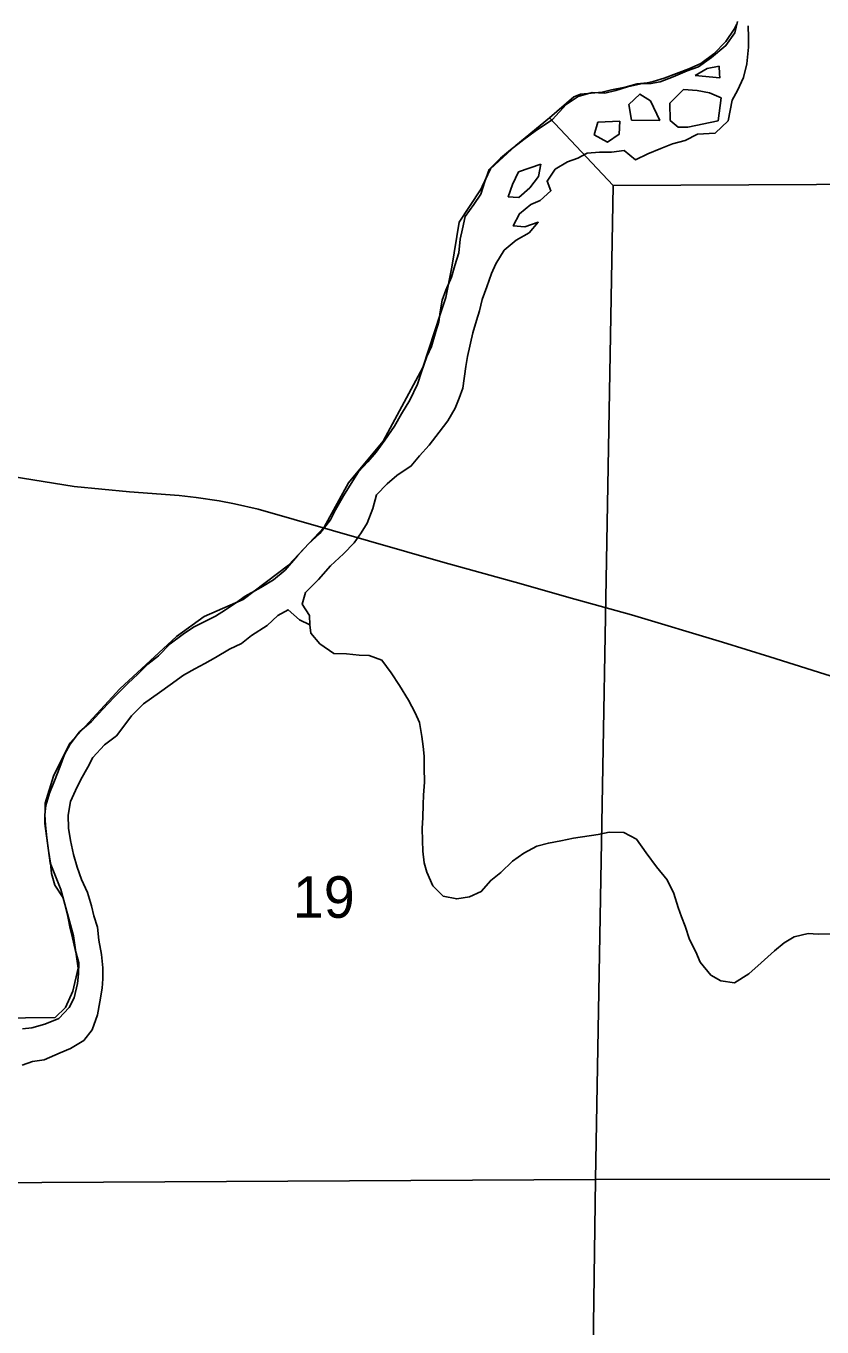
# Model space of a CAD drawing. Extents: x 1772825 to 1773716, y 1138558 to 1139032.
# Drawn here: x 1772828.223 to 1772828.624, y 1138562.068 to 1138562.723 of the extents above; entities that cross this region are included whole.
import ezdxf

# ---------------------------------------------------------------- set-up
doc = ezdxf.new("R2010")
doc.units = 0
for name, color, linetype in [('GM_X_Major_River', 7, 'Continuous'), ('GM_X_Minor_River', 7, 'Continuous'), ('GM_X_Rail_Line', 7, 'Continuous'), ('GM_X_Section', 7, 'Continuous'), ('GM_X_Section_Text', 7, 'Continuous')]:
    doc.layers.add(name, color=color, linetype=linetype)

msp = doc.modelspace()

# ---------------------------------------------------------------- linework, layer by layer
at = {"layer": 'GM_X_Major_River'}
msp.add_line((1772828.52194, 1138562.67523), (1772828.51074, 1138562.67475), dxfattribs=at)
for points in [[(1772828.58108, 1138562.72538), (1772828.57972, 1138562.7197), (1772828.57532, 1138562.71327), (1772828.56809, 1138562.70724), (1772828.56143, 1138562.70253), (1772828.55573, 1138562.70048), (1772828.54871, 1138562.69748), (1772828.54225, 1138562.69505), (1772828.53751, 1138562.69413), (1772828.5324, 1138562.69397), (1772828.52576, 1138562.69249), (1772828.51988, 1138562.69063), (1772828.51438, 1138562.68933), (1772828.50794, 1138562.68956), (1772828.50092, 1138562.6877), (1772828.49483, 1138562.68356), (1772828.48804, 1138562.67598)], [(1772828.57636, 1138562.6753), (1772828.57837, 1138562.68572), (1772828.58105, 1138562.69065), (1772828.58413, 1138562.69727), (1772828.58587, 1138562.7041), (1772828.58668, 1138562.71244), (1772828.58671, 1138562.71738), (1772828.58656, 1138562.72327)], [(1772828.57207, 1138562.69904), (1772828.57185, 1138562.70285), (1772828.56578, 1138562.70175), (1772828.55989, 1138562.69817)], [(1772828.55989, 1138562.69817), (1772828.57219, 1138562.69696), (1772828.57207, 1138562.69904)], [(1772828.542, 1138562.67556), (1772828.53727, 1138562.6854), (1772828.53199, 1138562.68885), (1772828.52646, 1138562.68356), (1772828.5278, 1138562.67567)], [(1772828.57132, 1138562.67534), (1772828.57289, 1138562.6869), (1772828.56703, 1138562.6894), (1772828.56079, 1138562.69058), (1772828.55397, 1138562.69119), (1772828.54714, 1138562.68424), (1772828.54722, 1138562.67553)], [(1772828.48804, 1138562.67598), (1772828.47922, 1138562.67024), (1772828.47349, 1138562.66592), (1772828.46682, 1138562.66085), (1772828.46185, 1138562.65652), (1772828.45612, 1138562.65087), (1772828.45399, 1138562.64482), (1772828.45185, 1138562.63838), (1772828.4484, 1138562.63329), (1772828.44399, 1138562.62725), (1772828.44262, 1138562.621), (1772828.44144, 1138562.61588), (1772828.44082, 1138562.60887), (1772828.43888, 1138562.60262), (1772828.43713, 1138562.59675), (1772828.43424, 1138562.59013), (1772828.43249, 1138562.58502), (1772828.4315, 1138562.57915), (1772828.43071, 1138562.57422), (1772828.42934, 1138562.5693), (1772828.42701, 1138562.56172), (1772828.4247, 1138562.55681), (1772828.42199, 1138562.54905), (1772828.42004, 1138562.5428), (1772828.41619, 1138562.53467), (1772828.41197, 1138562.52787), (1772828.40851, 1138562.52164), (1772828.40352, 1138562.51465), (1772828.3993, 1138562.50862), (1772828.39509, 1138562.50371), (1772828.39031, 1138562.49863), (1772828.38571, 1138562.49145), (1772828.38283, 1138562.48654), (1772828.37879, 1138562.47955), (1772828.37629, 1138562.47445), (1772828.37093, 1138562.46766), (1772828.365, 1138562.4622), (1772828.35965, 1138562.45636), (1772828.35334, 1138562.44919), (1772828.34761, 1138562.4443), (1772828.34113, 1138562.44037), (1772828.33332, 1138562.43606), (1772828.32836, 1138562.4325), (1772828.3234, 1138562.42912), (1772828.31826, 1138562.42593), (1772828.31235, 1138562.42294), (1772828.30721, 1138562.42051), (1772828.30206, 1138562.41695), (1772828.29558, 1138562.41206), (1772828.28965, 1138562.40604), (1772828.28431, 1138562.4019), (1772828.27934, 1138562.39701), (1772828.27418, 1138562.39211), (1772828.2673, 1138562.38515), (1772828.26157, 1138562.37912), (1772828.25583, 1138562.3729), (1772828.24991, 1138562.36782), (1772828.24512, 1138562.3616), (1772828.24224, 1138562.35631), (1772828.23991, 1138562.35006), (1772828.23721, 1138562.34306), (1772828.2347, 1138562.33682), (1772828.23295, 1138562.33076), (1772828.23234, 1138562.32602), (1772828.23268, 1138562.32071), (1772828.23339, 1138562.31444), (1772828.2343, 1138562.30798), (1772828.2352, 1138562.30171), (1772828.23573, 1138562.2964), (1772828.2374, 1138562.2905), (1772828.24171, 1138562.28421), (1772828.24392, 1138562.27489), (1772828.24521, 1138562.26881), (1772828.24631, 1138562.26406), (1772828.2476, 1138562.25817), (1772828.24945, 1138562.25151), (1772828.24941, 1138562.24601), (1772828.2488, 1138562.24108), (1772828.24723, 1138562.23388), (1772828.24473, 1138562.22897), (1772828.23938, 1138562.22351), (1772828.23234, 1138562.22053), (1772828.22587, 1138562.21868), (1772828.22112, 1138562.21833)], [(1772828.2402, 1138562.20624), (1772828.24534, 1138562.20828), (1772828.25201, 1138562.21241), (1772828.25622, 1138562.21769), (1772828.25893, 1138562.22526), (1772828.26012, 1138562.23189), (1772828.26131, 1138562.23871), (1772828.26153, 1138562.24345), (1772828.26157, 1138562.24895), (1772828.26086, 1138562.2556), (1772828.25958, 1138562.26282), (1772828.25887, 1138562.26947), (1772828.25702, 1138562.27517), (1772828.25591, 1138562.28012), (1772828.25388, 1138562.28696), (1772828.25089, 1138562.29344), (1772828.24866, 1138562.29971), (1772828.24681, 1138562.30599), (1772828.24534, 1138562.31302), (1772828.24425, 1138562.31929), (1772828.2441, 1138562.32574), (1772828.24529, 1138562.33276), (1772828.2478, 1138562.33824), (1772828.25049, 1138562.34372), (1772828.25414, 1138562.34995), (1772828.25665, 1138562.35487), (1772828.26239, 1138562.36128), (1772828.26849, 1138562.36578), (1772828.27213, 1138562.37069), (1772828.27596, 1138562.37578), (1772828.28208, 1138562.38181), (1772828.29009, 1138562.38763), (1772828.29543, 1138562.39138), (1772828.30229, 1138562.39626), (1772828.30801, 1138562.39945), (1772828.31296, 1138562.40226), (1772828.3183, 1138562.40525), (1772828.32535, 1138562.40937), (1772828.33144, 1138562.41217), (1772828.3364, 1138562.41631), (1772828.34441, 1138562.42137), (1772828.34975, 1138562.42626), (1772828.3549, 1138562.42926), (1772828.36055, 1138562.42409), (1772828.36585, 1138562.42159), (1772828.36569, 1138562.42633), (1772828.36194, 1138562.43205), (1772828.36369, 1138562.43792), (1772828.37019, 1138562.44451), (1772828.37631, 1138562.4513), (1772828.3828, 1138562.45732), (1772828.38816, 1138562.46297), (1772828.39161, 1138562.46788), (1772828.39468, 1138562.47279), (1772828.39758, 1138562.48017), (1772828.39934, 1138562.48717), (1772828.40469, 1138562.49264), (1772828.40965, 1138562.49677), (1772828.4169, 1138562.50165), (1772828.42111, 1138562.50674), (1772828.42589, 1138562.51202), (1772828.43087, 1138562.51862), (1772828.43528, 1138562.52428), (1772828.43893, 1138562.53071), (1772828.44105, 1138562.53581), (1772828.4428, 1138562.54073), (1772828.44439, 1138562.55173), (1772828.44519, 1138562.55665), (1772828.44793, 1138562.56859), (1772828.44968, 1138562.57483), (1772828.45124, 1138562.57976), (1772828.45261, 1138562.58544), (1772828.45493, 1138562.59187), (1772828.45726, 1138562.5985), (1772828.45938, 1138562.60341), (1772828.4636, 1138562.61021), (1772828.46971, 1138562.61529), (1772828.47619, 1138562.61904), (1772828.48078, 1138562.62431), (1772828.47412, 1138562.62209), (1772828.46824, 1138562.62251), (1772828.47132, 1138562.62856), (1772828.47705, 1138562.63326), (1772828.48181, 1138562.63531), (1772828.48716, 1138562.6402), (1772828.48529, 1138562.64496), (1772828.48932, 1138562.651), (1772828.49561, 1138562.65475), (1772828.50075, 1138562.65661), (1772828.50551, 1138562.65904), (1772828.51158, 1138562.65956), (1772828.51765, 1138562.65952), (1772828.52411, 1138562.66042), (1772828.52977, 1138562.65582), (1772828.53605, 1138562.65881), (1772828.54252, 1138562.66142), (1772828.54842, 1138562.66384), (1772828.5547, 1138562.6655), (1772828.56098, 1138562.66868), (1772828.56984, 1138562.66918), (1772828.57636, 1138562.6753)], [(1772828.51074, 1138562.67475), (1772828.50899, 1138562.66831), (1772828.51561, 1138562.66466), (1772828.52152, 1138562.6686), (1772828.52194, 1138562.67523)], [(1772828.5278, 1138562.67567), (1772828.542, 1138562.67556)], [(1772828.54722, 1138562.67553), (1772828.55133, 1138562.67217), (1772828.55607, 1138562.67213), (1772828.57132, 1138562.67534)], [(1772828.48213, 1138562.65352), (1772828.47091, 1138562.64962), (1772828.46783, 1138562.64339), (1772828.46569, 1138562.63714), (1772828.46827, 1138562.63694)], [(1772828.46827, 1138562.63694), (1772828.471, 1138562.63672), (1772828.47654, 1138562.64161), (1772828.48095, 1138562.64727), (1772828.48213, 1138562.65352)], [(1772828.22099, 1138562.19993), (1772828.22613, 1138562.20179), (1772828.23202, 1138562.20269), (1772828.2402, 1138562.20624)]]:
    msp.add_lwpolyline(points, dxfattribs=at)
at = {"layer": 'GM_X_Minor_River'}
msp.add_lwpolyline([(1772828.36585, 1138562.42159), (1772828.36639, 1138562.41741), (1772828.3709, 1138562.41206), (1772828.37789, 1138562.40726), (1772828.38434, 1138562.40703), (1772828.39059, 1138562.40641), (1772828.39572, 1138562.40618), (1772828.40215, 1138562.40385), (1772828.40685, 1138562.39756), (1772828.41097, 1138562.39108), (1772828.41547, 1138562.38364), (1772828.41884, 1138562.37735), (1772828.42108, 1138562.3724), (1772828.42217, 1138562.36537), (1772828.42289, 1138562.36044), (1772828.42343, 1138562.3555), (1772828.42338, 1138562.34962), (1772828.42352, 1138562.3424), (1772828.4231, 1138562.33596), (1772828.42287, 1138562.33122), (1772828.42263, 1138562.32458), (1772828.4224, 1138562.31907), (1772828.42255, 1138562.313), (1772828.4227, 1138562.30769), (1772828.42342, 1138562.3018), (1772828.42471, 1138562.29705), (1772828.4277, 1138562.29019), (1772828.43297, 1138562.28503), (1772828.43979, 1138562.28365), (1772828.44625, 1138562.28474), (1772828.45215, 1138562.28735), (1772828.45694, 1138562.29301), (1772828.4619, 1138562.29695), (1772828.46782, 1138562.3026), (1772828.47354, 1138562.30673), (1772828.48002, 1138562.31029), (1772828.48591, 1138562.31176), (1772828.49218, 1138562.31285), (1772828.49864, 1138562.31432), (1772828.51099, 1138562.31613), (1772828.5165, 1138562.31722), (1772828.5239, 1138562.31717), (1772828.53032, 1138562.3137), (1772828.53521, 1138562.30684), (1772828.54028, 1138562.29978), (1772828.54573, 1138562.29329), (1772828.5491, 1138562.28643), (1772828.55133, 1138562.27939), (1772828.553, 1138562.27464), (1772828.55486, 1138562.26988), (1772828.5569, 1138562.26322), (1772828.56008, 1138562.25694), (1772828.56232, 1138562.2518), (1772828.56777, 1138562.2453), (1772828.57269, 1138562.24242), (1772828.5797, 1138562.24142), (1772828.58675, 1138562.24592), (1772828.59306, 1138562.25156), (1772828.59974, 1138562.25759), (1772828.6047, 1138562.26153), (1772828.60966, 1138562.26453), (1772828.61669, 1138562.26619), (1772828.62181, 1138562.26596), (1772828.62788, 1138562.2661)], dxfattribs=at)
at = {"layer": 'GM_X_Rail_Line'}
for points in [[(1772828.16182, 1138562.50319), (1772828.21603, 1138562.49624), (1772828.24712, 1138562.49124), (1772828.27498, 1138562.48855), (1772828.30004, 1138562.48673), (1772828.30855, 1138562.48569), (1772828.3202, 1138562.48404), (1772828.32789, 1138562.48261), (1772828.33976, 1138562.47987), (1772828.43277, 1138562.45322)], [(1772828.43277, 1138562.45322), (1772828.47216, 1138562.4423), (1772828.4962, 1138562.43544), (1772828.52782, 1138562.42662), (1772828.57356, 1138562.41289), (1772828.59734, 1138562.4055), (1772828.63738, 1138562.393)]]:
    msp.add_lwpolyline(points, dxfattribs=at)
at = {"layer": 'GM_X_Section'}
for points in [[(1772829.04388, 1138563.14186), (1772829.03068, 1138562.64534), (1772828.51851, 1138562.64277), (1772828.4865, 1138562.67693), (1772828.49871, 1138562.68748), (1772828.50213, 1138562.68878), (1772828.51294, 1138562.68983), (1772828.51768, 1138562.69093), (1772828.52452, 1138562.6924), (1772828.53059, 1138562.69406), (1772828.53571, 1138562.69458), (1772828.53875, 1138562.69513), (1772828.54426, 1138562.69679), (1772828.55661, 1138562.70162), (1772828.56269, 1138562.70423), (1772828.56917, 1138562.70911), (1772828.57528, 1138562.71531), (1772828.5795, 1138562.72153), (1772828.58084, 1138562.72399)], [(1772827.98424, 1138562.22106), (1772828.23758, 1138562.22388), (1772828.24274, 1138562.22896), (1772828.24659, 1138562.23727), (1772828.24914, 1138562.2488), (1772828.2468, 1138562.26512), (1772828.24053, 1138562.28847), (1772828.23514, 1138562.30177), (1772828.23245, 1138562.32169), (1772828.23252, 1138562.33192), (1772828.23679, 1138562.34553), (1772828.24507, 1138562.36214), (1772828.2701, 1138562.38942), (1772828.29872, 1138562.41573), (1772828.31262, 1138562.42586), (1772828.3322, 1138562.43443), (1772828.35507, 1138562.45169), (1772828.37303, 1138562.47088), (1772828.38532, 1138562.49314), (1772828.40272, 1138562.51404), (1772828.42271, 1138562.55122), (1772828.43163, 1138562.57843), (1772828.43434, 1138562.58637), (1772828.4373, 1138562.6017), (1772828.44107, 1138562.62441), (1772828.4518, 1138562.64062), (1772828.45257, 1138562.64232), (1772828.45681, 1138562.65119), (1772828.46959, 1138562.66303), (1772828.4865, 1138562.67693), (1772828.51851, 1138562.64277), (1772828.50962, 1138562.14244), (1772827.98305, 1138562.13959)]]:
    msp.add_lwpolyline(points, dxfattribs=at)
for points in [[(1772829.03068, 1138562.64534), (1772829.02215, 1138562.14292), (1772828.50962, 1138562.14244), (1772828.51851, 1138562.64277)], [(1772828.50962, 1138562.14244), (1772828.50281, 1138561.64361), (1772827.9835, 1138561.6464), (1772827.98305, 1138562.13959)], [(1772829.02215, 1138562.14292), (1772829.0119, 1138561.63975), (1772828.50281, 1138561.64361), (1772828.50962, 1138562.14244)]]:
    msp.add_lwpolyline(points, close=True, dxfattribs=at)

# ---------------------------------------------------------------- texts
at = {"layer": 'GM_X_Section_Text'}
msp.add_text('19', height=0.020928, rotation=0.00001, dxfattribs=at).set_placement((1772828.35729, 1138562.27415))

doc.saveas('drawing.dxf')
